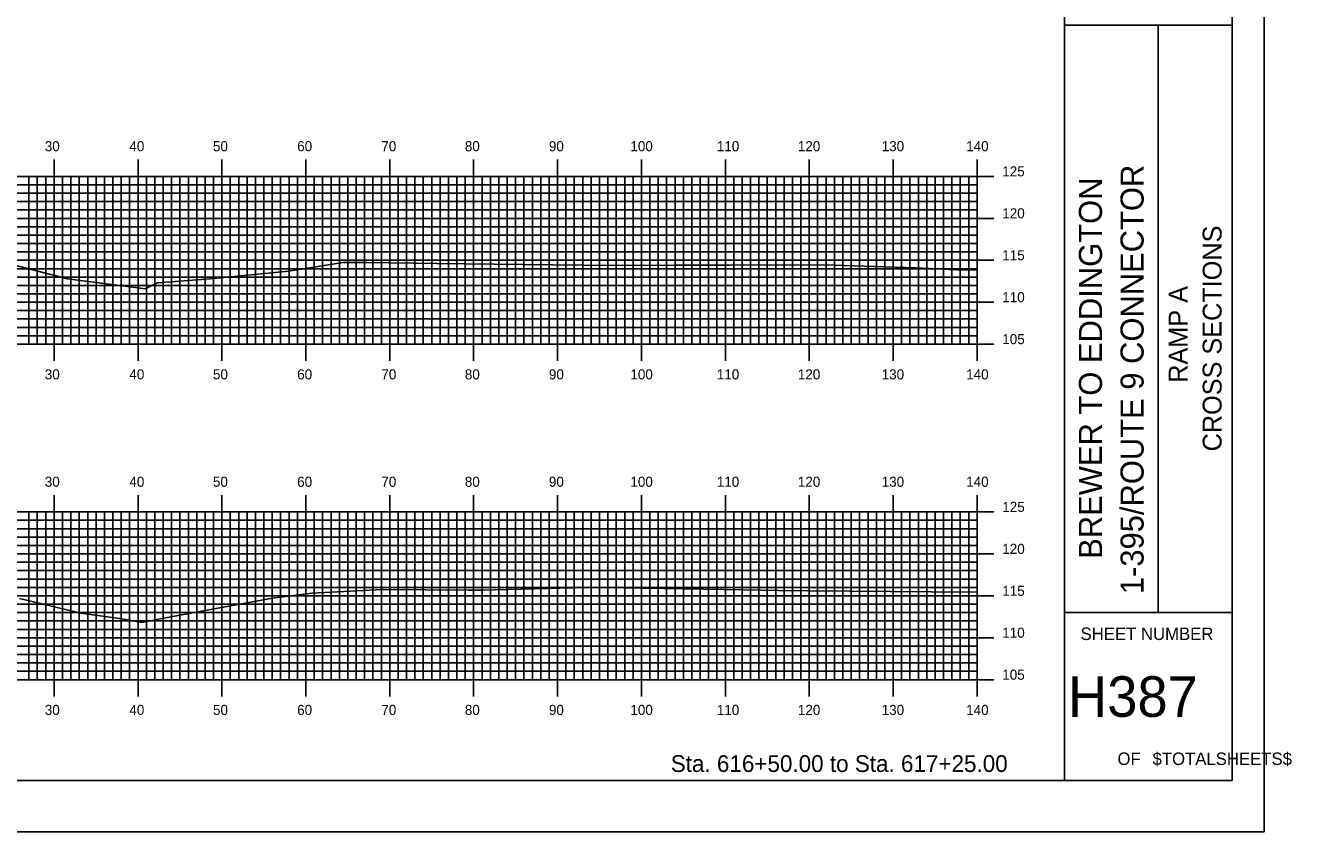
# Model space of a CAD drawing. Extents: x 844930 to 845273, y 363538 to 363758.
# Drawn here: x 845122 to 845273, y 363537.6 to 363633.7 of the extents above; entities that cross this region are included whole.
import ezdxf

# ---------------------------------------------------------------- set-up
doc = ezdxf.new("R2010")
doc.units = 0
for name, color, linetype in [('BORDER', 7, 'Continuous'), ('H_V ANNOTATION', 7, 'Continuous'), ('MAJOR', 7, 'Continuous'), ('MINOR', 7, 'Continuous'), ('PLOT BOUNDARY', 7, 'Continuous'), ('S_Roadway_Centerline', 7, 'Continuous')]:
    doc.layers.add(name, color=color, linetype=linetype)

msp = doc.modelspace()

# ---------------------------------------------------------------- linework, layer by layer
at = {"layer": 'BORDER'}
for p, q in [((845245.88, 363543.72), (845245.88, 363753.72)), ((845245.88, 363633.73), (845265.88, 363633.73)), ((845257.06, 363563.73), (845257.06, 363633.73)), ((845245.88, 363563.73), (845265.88, 363563.73))]:
    msp.add_line(p, q, dxfattribs=at)
msp.add_lwpolyline([(844945.88, 363543.72), (845265.88, 363543.72), (845265.88, 363753.72), (844945.88, 363753.72)], close=True, dxfattribs=at)
at = {"layer": 'MAJOR'}
for p, q in [((845125.48, 363617.73), (845125.48, 363615.72)), ((845135.48, 363617.73), (845135.48, 363615.72)), ((845145.48, 363617.73), (845145.48, 363615.72)), ((845155.48, 363617.73), (845155.48, 363615.72)), ((845165.48, 363617.73), (845165.48, 363615.72)), ((845175.48, 363617.73), (845175.48, 363615.72)), ((845185.48, 363617.73), (845185.48, 363615.72)), ((845195.48, 363617.73), (845195.48, 363615.72)), ((845205.48, 363617.73), (845205.48, 363615.72)), ((845215.48, 363617.73), (845215.48, 363615.72)), ((845225.48, 363617.73), (845225.48, 363615.72)), ((845235.48, 363617.73), (845235.48, 363615.72)), ((844955.48, 363615.72), (845235.48, 363615.72)), ((844955.48, 363615.72), (845235.48, 363615.72)), ((845125.48, 363595.72), (845125.48, 363615.72)), ((845135.48, 363595.72), (845135.48, 363615.72)), ((845145.48, 363595.72), (845145.48, 363615.72)), ((845155.48, 363595.72), (845155.48, 363615.72)), ((845165.48, 363595.72), (845165.48, 363615.72)), ((845175.48, 363595.72), (845175.48, 363615.72)), ((845185.48, 363595.72), (845185.48, 363615.72)), ((845195.48, 363595.72), (845195.48, 363615.72)), ((845205.48, 363595.72), (845205.48, 363615.72)), ((845215.48, 363595.72), (845215.48, 363615.72)), ((845225.48, 363595.72), (845225.48, 363615.72)), ((845237.48, 363615.72), (845233.47, 363615.72)), ((845235.48, 363595.72), (845235.48, 363615.72)), ((845235.48, 363595.72), (845235.48, 363615.72)), ((844955.48, 363610.72), (845235.48, 363610.72)), ((845237.48, 363610.72), (845233.47, 363610.72)), ((844955.48, 363605.72), (845235.48, 363605.72)), ((845237.48, 363605.72), (845233.47, 363605.72)), ((844955.48, 363600.72), (845235.48, 363600.72)), ((845237.48, 363600.72), (845233.47, 363600.72)), ((844955.48, 363595.72), (845235.48, 363595.72)), ((844955.48, 363595.72), (845235.48, 363595.72)), ((845125.48, 363593.72), (845125.48, 363595.72)), ((845135.48, 363593.72), (845135.48, 363595.72)), ((845145.48, 363593.72), (845145.48, 363595.72)), ((845155.48, 363593.72), (845155.48, 363595.72)), ((845165.48, 363593.72), (845165.48, 363595.72)), ((845175.48, 363593.72), (845175.48, 363595.72)), ((845185.48, 363593.72), (845185.48, 363595.72)), ((845195.48, 363593.72), (845195.48, 363595.72)), ((845205.48, 363593.72), (845205.48, 363595.72)), ((845215.48, 363593.72), (845215.48, 363595.72)), ((845225.48, 363593.72), (845225.48, 363595.72)), ((845237.48, 363595.72), (845233.47, 363595.72)), ((845235.48, 363593.72), (845235.48, 363595.72)), ((845125.48, 363577.73), (845125.48, 363575.72)), ((845135.48, 363577.73), (845135.48, 363575.72)), ((845145.48, 363577.73), (845145.48, 363575.72)), ((845155.48, 363577.73), (845155.48, 363575.72)), ((845165.48, 363577.73), (845165.48, 363575.72)), ((845175.48, 363577.73), (845175.48, 363575.72)), ((845185.48, 363577.73), (845185.48, 363575.72)), ((845195.48, 363577.73), (845195.48, 363575.72)), ((845205.48, 363577.73), (845205.48, 363575.72)), ((845215.48, 363577.73), (845215.48, 363575.72)), ((845225.48, 363577.73), (845225.48, 363575.72)), ((845235.48, 363577.73), (845235.48, 363575.72)), ((844955.48, 363575.72), (845235.48, 363575.72)), ((844955.48, 363575.72), (845235.48, 363575.72)), ((845125.48, 363555.72), (845125.48, 363575.72)), ((845135.48, 363555.72), (845135.48, 363575.72)), ((845145.48, 363555.72), (845145.48, 363575.72)), ((845155.48, 363555.72), (845155.48, 363575.72)), ((845165.48, 363555.72), (845165.48, 363575.72)), ((845175.48, 363555.72), (845175.48, 363575.72)), ((845185.48, 363555.72), (845185.48, 363575.72)), ((845195.48, 363555.72), (845195.48, 363575.72)), ((845205.48, 363555.72), (845205.48, 363575.72)), ((845215.48, 363555.72), (845215.48, 363575.72)), ((845225.48, 363555.72), (845225.48, 363575.72)), ((845237.48, 363575.72), (845233.47, 363575.72)), ((845235.48, 363555.72), (845235.48, 363575.72)), ((845235.48, 363555.72), (845235.48, 363575.72)), ((844955.48, 363570.72), (845235.48, 363570.72)), ((845237.48, 363570.72), (845233.47, 363570.72)), ((844955.48, 363565.72), (845235.48, 363565.72)), ((845237.48, 363565.72), (845233.47, 363565.72)), ((844955.48, 363560.72), (845235.48, 363560.72)), ((845237.48, 363560.72), (845233.47, 363560.72)), ((844955.48, 363555.72), (845235.48, 363555.72)), ((844955.48, 363555.72), (845235.48, 363555.72)), ((845125.48, 363553.72), (845125.48, 363555.72)), ((845135.48, 363553.72), (845135.48, 363555.72)), ((845145.48, 363553.72), (845145.48, 363555.72)), ((845155.48, 363553.72), (845155.48, 363555.72)), ((845165.48, 363553.72), (845165.48, 363555.72)), ((845175.48, 363553.72), (845175.48, 363555.72)), ((845185.48, 363553.72), (845185.48, 363555.72)), ((845195.48, 363553.72), (845195.48, 363555.72)), ((845205.48, 363553.72), (845205.48, 363555.72)), ((845215.48, 363553.72), (845215.48, 363555.72)), ((845225.48, 363553.72), (845225.48, 363555.72)), ((845237.48, 363555.72), (845233.47, 363555.72)), ((845235.48, 363553.72), (845235.48, 363555.72))]:
    msp.add_line(p, q, dxfattribs=at)
at = {"layer": 'MINOR'}
for p, q in [((845122.48, 363595.72), (845122.48, 363615.72)), ((845123.48, 363595.72), (845123.48, 363615.72)), ((845124.48, 363595.72), (845124.48, 363615.72)), ((845126.48, 363595.72), (845126.48, 363615.72)), ((845127.48, 363595.72), (845127.48, 363615.72)), ((845128.48, 363595.72), (845128.48, 363615.72)), ((845129.48, 363595.72), (845129.48, 363615.72)), ((845130.48, 363595.72), (845130.48, 363615.72)), ((845131.48, 363595.72), (845131.48, 363615.72)), ((845132.48, 363595.72), (845132.48, 363615.72)), ((845133.48, 363595.72), (845133.48, 363615.72)), ((845134.48, 363595.72), (845134.48, 363615.72)), ((845136.48, 363595.72), (845136.48, 363615.72)), ((845137.48, 363595.72), (845137.48, 363615.72)), ((845138.48, 363595.72), (845138.48, 363615.72)), ((845139.48, 363595.72), (845139.48, 363615.72)), ((845140.48, 363595.72), (845140.48, 363615.72)), ((845141.48, 363595.72), (845141.48, 363615.72)), ((845142.48, 363595.72), (845142.48, 363615.72)), ((845143.48, 363595.72), (845143.48, 363615.72)), ((845144.48, 363595.72), (845144.48, 363615.72)), ((845146.48, 363595.72), (845146.48, 363615.72)), ((845147.48, 363595.72), (845147.48, 363615.72)), ((845148.48, 363595.72), (845148.48, 363615.72)), ((845149.48, 363595.72), (845149.48, 363615.72)), ((845150.48, 363595.72), (845150.48, 363615.72)), ((845151.48, 363595.72), (845151.48, 363615.72)), ((845152.48, 363595.72), (845152.48, 363615.72)), ((845153.48, 363595.72), (845153.48, 363615.72)), ((845154.48, 363595.72), (845154.48, 363615.72)), ((845156.48, 363595.72), (845156.48, 363615.72)), ((845157.48, 363595.72), (845157.48, 363615.72)), ((845158.48, 363595.72), (845158.48, 363615.72)), ((845159.48, 363595.72), (845159.48, 363615.72)), ((845160.48, 363595.72), (845160.48, 363615.72)), ((845161.48, 363595.72), (845161.48, 363615.72)), ((845162.48, 363595.72), (845162.48, 363615.72)), ((845163.48, 363595.72), (845163.48, 363615.72)), ((845164.48, 363595.72), (845164.48, 363615.72)), ((845166.48, 363595.72), (845166.48, 363615.72)), ((845167.48, 363595.72), (845167.48, 363615.72)), ((845168.48, 363595.72), (845168.48, 363615.72)), ((845169.48, 363595.72), (845169.48, 363615.72)), ((845170.48, 363595.72), (845170.48, 363615.72)), ((845171.48, 363595.72), (845171.48, 363615.72)), ((845172.48, 363595.72), (845172.48, 363615.72)), ((845173.48, 363595.72), (845173.48, 363615.72)), ((845174.48, 363595.72), (845174.48, 363615.72)), ((845176.48, 363595.72), (845176.48, 363615.72)), ((845177.48, 363595.72), (845177.48, 363615.72)), ((845178.48, 363595.72), (845178.48, 363615.72)), ((845179.48, 363595.72), (845179.48, 363615.72)), ((845180.48, 363595.72), (845180.48, 363615.72)), ((845181.48, 363595.72), (845181.48, 363615.72)), ((845182.48, 363595.72), (845182.48, 363615.72)), ((845183.48, 363595.72), (845183.48, 363615.72)), ((845184.48, 363595.72), (845184.48, 363615.72)), ((845186.48, 363595.72), (845186.48, 363615.72)), ((845187.48, 363595.72), (845187.48, 363615.72)), ((845188.48, 363595.72), (845188.48, 363615.72)), ((845189.48, 363595.72), (845189.48, 363615.72)), ((845190.48, 363595.72), (845190.48, 363615.72)), ((845191.48, 363595.72), (845191.48, 363615.72)), ((845192.48, 363595.72), (845192.48, 363615.72)), ((845193.48, 363595.72), (845193.48, 363615.72)), ((845194.48, 363595.72), (845194.48, 363615.72)), ((845196.48, 363595.72), (845196.48, 363615.72)), ((845197.48, 363595.72), (845197.48, 363615.72)), ((845198.48, 363595.72), (845198.48, 363615.72)), ((845199.48, 363595.72), (845199.48, 363615.72)), ((845200.48, 363595.72), (845200.48, 363615.72)), ((845201.48, 363595.72), (845201.48, 363615.72)), ((845202.48, 363595.72), (845202.48, 363615.72)), ((845203.48, 363595.72), (845203.48, 363615.72)), ((845204.48, 363595.72), (845204.48, 363615.72)), ((845206.48, 363595.72), (845206.48, 363615.72)), ((845207.48, 363595.72), (845207.48, 363615.72)), ((845208.48, 363595.72), (845208.48, 363615.72)), ((845209.48, 363595.72), (845209.48, 363615.72)), ((845210.48, 363595.72), (845210.48, 363615.72)), ((845211.48, 363595.72), (845211.48, 363615.72)), ((845212.48, 363595.72), (845212.48, 363615.72)), ((845213.48, 363595.72), (845213.48, 363615.72)), ((845214.48, 363595.72), (845214.48, 363615.72)), ((845216.48, 363595.72), (845216.48, 363615.72)), ((845217.48, 363595.72), (845217.48, 363615.72)), ((845218.48, 363595.72), (845218.48, 363615.72)), ((845219.48, 363595.72), (845219.48, 363615.72)), ((845220.48, 363595.72), (845220.48, 363615.72)), ((845221.48, 363595.72), (845221.48, 363615.72)), ((845222.48, 363595.72), (845222.48, 363615.72)), ((845223.48, 363595.72), (845223.48, 363615.72)), ((845224.48, 363595.72), (845224.48, 363615.72)), ((845226.48, 363595.72), (845226.48, 363615.72)), ((845227.48, 363595.72), (845227.48, 363615.72)), ((845228.48, 363595.72), (845228.48, 363615.72)), ((845229.48, 363595.72), (845229.48, 363615.72)), ((845230.48, 363595.72), (845230.48, 363615.72)), ((845231.48, 363595.72), (845231.48, 363615.72)), ((845232.48, 363595.72), (845232.48, 363615.72)), ((845233.48, 363595.72), (845233.48, 363615.72)), ((845234.48, 363595.72), (845234.48, 363615.72)), ((844955.48, 363614.72), (845235.48, 363614.72)), ((845235.48, 363614.72), (845233.47, 363614.72)), ((844955.48, 363613.72), (845235.48, 363613.72)), ((844955.48, 363612.72), (845235.48, 363612.72)), ((845235.48, 363613.72), (845233.47, 363613.72)), ((845235.48, 363612.72), (845233.47, 363612.72)), ((844955.48, 363611.72), (845235.48, 363611.72)), ((845235.48, 363611.72), (845233.47, 363611.72)), ((844955.48, 363609.72), (845235.48, 363609.72)), ((845235.48, 363609.72), (845233.47, 363609.72)), ((844955.48, 363608.72), (845235.48, 363608.72)), ((845235.48, 363608.72), (845233.47, 363608.72)), ((844955.48, 363607.72), (845235.48, 363607.72)), ((844955.48, 363606.72), (845235.48, 363606.72)), ((845235.48, 363607.72), (845233.47, 363607.72)), ((845235.48, 363606.72), (845233.47, 363606.72)), ((844955.48, 363604.72), (845235.48, 363604.72)), ((844955.48, 363603.72), (845235.48, 363603.72)), ((845235.48, 363604.72), (845233.47, 363604.72)), ((845235.48, 363603.72), (845233.47, 363603.72)), ((844955.48, 363602.72), (845235.48, 363602.72)), ((845235.48, 363602.72), (845233.47, 363602.72)), ((844955.48, 363601.72), (845235.48, 363601.72)), ((845235.48, 363601.72), (845233.47, 363601.72)), ((844955.48, 363599.72), (845235.48, 363599.72)), ((845235.48, 363599.72), (845233.47, 363599.72)), ((844955.48, 363598.72), (845235.48, 363598.72)), ((844955.48, 363597.72), (845235.48, 363597.72)), ((845235.48, 363598.72), (845233.47, 363598.72)), ((845235.48, 363597.72), (845233.47, 363597.72)), ((844955.48, 363596.72), (845235.48, 363596.72)), ((845235.48, 363596.72), (845233.47, 363596.72)), ((845122.48, 363555.72), (845122.48, 363575.72)), ((845123.48, 363555.72), (845123.48, 363575.72)), ((845124.48, 363555.72), (845124.48, 363575.72)), ((845126.48, 363555.72), (845126.48, 363575.72)), ((845127.48, 363555.72), (845127.48, 363575.72)), ((845128.48, 363555.72), (845128.48, 363575.72)), ((845129.48, 363555.72), (845129.48, 363575.72)), ((845130.48, 363555.72), (845130.48, 363575.72)), ((845131.48, 363555.72), (845131.48, 363575.72)), ((845132.48, 363555.72), (845132.48, 363575.72)), ((845133.48, 363555.72), (845133.48, 363575.72)), ((845134.48, 363555.72), (845134.48, 363575.72)), ((845136.48, 363555.72), (845136.48, 363575.72)), ((845137.48, 363555.72), (845137.48, 363575.72)), ((845138.48, 363555.72), (845138.48, 363575.72)), ((845139.48, 363555.72), (845139.48, 363575.72)), ((845140.48, 363555.72), (845140.48, 363575.72)), ((845141.48, 363555.72), (845141.48, 363575.72)), ((845142.48, 363555.72), (845142.48, 363575.72)), ((845143.48, 363555.72), (845143.48, 363575.72)), ((845144.48, 363555.72), (845144.48, 363575.72)), ((845146.48, 363555.72), (845146.48, 363575.72)), ((845147.48, 363555.72), (845147.48, 363575.72)), ((845148.48, 363555.72), (845148.48, 363575.72)), ((845149.48, 363555.72), (845149.48, 363575.72)), ((845150.48, 363555.72), (845150.48, 363575.72)), ((845151.48, 363555.72), (845151.48, 363575.72)), ((845152.48, 363555.72), (845152.48, 363575.72)), ((845153.48, 363555.72), (845153.48, 363575.72)), ((845154.48, 363555.72), (845154.48, 363575.72)), ((845156.48, 363555.72), (845156.48, 363575.72)), ((845157.48, 363555.72), (845157.48, 363575.72)), ((845158.48, 363555.72), (845158.48, 363575.72)), ((845159.48, 363555.72), (845159.48, 363575.72)), ((845160.48, 363555.72), (845160.48, 363575.72)), ((845161.48, 363555.72), (845161.48, 363575.72)), ((845162.48, 363555.72), (845162.48, 363575.72)), ((845163.48, 363555.72), (845163.48, 363575.72)), ((845164.48, 363555.72), (845164.48, 363575.72)), ((845166.48, 363555.72), (845166.48, 363575.72)), ((845167.48, 363555.72), (845167.48, 363575.72)), ((845168.48, 363555.72), (845168.48, 363575.72)), ((845169.48, 363555.72), (845169.48, 363575.72)), ((845170.48, 363555.72), (845170.48, 363575.72)), ((845171.48, 363555.72), (845171.48, 363575.72)), ((845172.48, 363555.72), (845172.48, 363575.72)), ((845173.48, 363555.72), (845173.48, 363575.72)), ((845174.48, 363555.72), (845174.48, 363575.72)), ((845176.48, 363555.72), (845176.48, 363575.72)), ((845177.48, 363555.72), (845177.48, 363575.72)), ((845178.48, 363555.72), (845178.48, 363575.72)), ((845179.48, 363555.72), (845179.48, 363575.72)), ((845180.48, 363555.72), (845180.48, 363575.72)), ((845181.48, 363555.72), (845181.48, 363575.72)), ((845182.48, 363555.72), (845182.48, 363575.72)), ((845183.48, 363555.72), (845183.48, 363575.72)), ((845184.48, 363555.72), (845184.48, 363575.72)), ((845186.48, 363555.72), (845186.48, 363575.72)), ((845187.48, 363555.72), (845187.48, 363575.72)), ((845188.48, 363555.72), (845188.48, 363575.72)), ((845189.48, 363555.72), (845189.48, 363575.72)), ((845190.48, 363555.72), (845190.48, 363575.72)), ((845191.48, 363555.72), (845191.48, 363575.72)), ((845192.48, 363555.72), (845192.48, 363575.72)), ((845193.48, 363555.72), (845193.48, 363575.72)), ((845194.48, 363555.72), (845194.48, 363575.72)), ((845196.48, 363555.72), (845196.48, 363575.72)), ((845197.48, 363555.72), (845197.48, 363575.72)), ((845198.48, 363555.72), (845198.48, 363575.72)), ((845199.48, 363555.72), (845199.48, 363575.72)), ((845200.48, 363555.72), (845200.48, 363575.72)), ((845201.48, 363555.72), (845201.48, 363575.72)), ((845202.48, 363555.72), (845202.48, 363575.72)), ((845203.48, 363555.72), (845203.48, 363575.72)), ((845204.48, 363555.72), (845204.48, 363575.72)), ((845206.48, 363555.72), (845206.48, 363575.72)), ((845207.48, 363555.72), (845207.48, 363575.72)), ((845208.48, 363555.72), (845208.48, 363575.72)), ((845209.48, 363555.72), (845209.48, 363575.72)), ((845210.48, 363555.72), (845210.48, 363575.72)), ((845211.48, 363555.72), (845211.48, 363575.72)), ((845212.48, 363555.72), (845212.48, 363575.72)), ((845213.48, 363555.72), (845213.48, 363575.72)), ((845214.48, 363555.72), (845214.48, 363575.72)), ((845216.48, 363555.72), (845216.48, 363575.72)), ((845217.48, 363555.72), (845217.48, 363575.72)), ((845218.48, 363555.72), (845218.48, 363575.72)), ((845219.48, 363555.72), (845219.48, 363575.72)), ((845220.48, 363555.72), (845220.48, 363575.72)), ((845221.48, 363555.72), (845221.48, 363575.72)), ((845222.48, 363555.72), (845222.48, 363575.72)), ((845223.48, 363555.72), (845223.48, 363575.72)), ((845224.48, 363555.72), (845224.48, 363575.72)), ((845226.48, 363555.72), (845226.48, 363575.72)), ((845227.48, 363555.72), (845227.48, 363575.72)), ((845228.48, 363555.72), (845228.48, 363575.72)), ((845229.48, 363555.72), (845229.48, 363575.72)), ((845230.48, 363555.72), (845230.48, 363575.72)), ((845231.48, 363555.72), (845231.48, 363575.72)), ((845232.48, 363555.72), (845232.48, 363575.72)), ((845233.48, 363555.72), (845233.48, 363575.72)), ((845234.48, 363555.72), (845234.48, 363575.72)), ((844955.48, 363574.72), (845235.48, 363574.72)), ((844955.48, 363573.72), (845235.48, 363573.72)), ((845235.48, 363574.72), (845233.47, 363574.72)), ((845235.48, 363573.72), (845233.47, 363573.72)), ((844955.48, 363572.72), (845235.48, 363572.72)), ((845235.48, 363572.72), (845233.47, 363572.72)), ((844955.48, 363571.72), (845235.48, 363571.72)), ((845235.48, 363571.72), (845233.47, 363571.72)), ((844955.48, 363569.72), (845235.48, 363569.72)), ((845235.48, 363569.72), (845233.47, 363569.72)), ((844955.48, 363568.72), (845235.48, 363568.72)), ((844955.48, 363567.72), (845235.48, 363567.72)), ((845235.48, 363568.72), (845233.47, 363568.72)), ((845235.48, 363567.72), (845233.47, 363567.72)), ((844955.48, 363566.72), (845235.48, 363566.72)), ((845235.48, 363566.72), (845233.47, 363566.72)), ((844955.48, 363564.72), (845235.48, 363564.72)), ((845235.48, 363564.72), (845233.47, 363564.72)), ((844955.48, 363563.72), (845235.48, 363563.72)), ((844955.48, 363562.72), (845235.48, 363562.72)), ((845235.48, 363563.72), (845233.47, 363563.72)), ((845235.48, 363562.72), (845233.47, 363562.72)), ((844955.48, 363561.72), (845235.48, 363561.72)), ((845235.48, 363561.72), (845233.47, 363561.72)), ((844955.48, 363559.72), (845235.48, 363559.72)), ((845235.48, 363559.72), (845233.47, 363559.72)), ((844955.48, 363558.72), (845235.48, 363558.72)), ((845235.48, 363558.72), (845233.47, 363558.72)), ((844955.48, 363557.72), (845235.48, 363557.72)), ((844955.48, 363556.72), (845235.48, 363556.72)), ((845235.48, 363557.72), (845233.47, 363557.72)), ((845235.48, 363556.72), (845233.47, 363556.72))]:
    msp.add_line(p, q, dxfattribs=at)
at = {"layer": 'PLOT BOUNDARY'}
msp.add_lwpolyline([(844929.69, 363537.6), (845269.69, 363537.6), (845269.69, 363757.6), (844929.69, 363757.6)], close=True, dxfattribs=at)
at = {"layer": 'S_Roadway_Centerline'}
for points in [[(845118.72, 363605.64), (845127.06, 363603.52), (845129.54, 363603.19), (845135.48, 363602.43), (845136.34, 363602.32), (845137.82, 363603.05), (845144.09, 363603.5), (845153.41, 363604.42), (845159.88, 363605.46), (845162.78, 363605.44), (845171.09, 363605.35), (845181.39, 363605.22), (845191.89, 363605.1), (845199.38, 363605.12), (845206, 363605.13), (845217.18, 363605.18), (845228.2, 363604.82), (845233, 363604.59), (845235.48, 363604.54)], [(845121.35, 363565.42), (845128.67, 363563.67), (845133.56, 363562.96), (845135.93, 363562.55), (845139.6, 363563.25), (845140.05, 363563.32), (845141.97, 363563.7), (845151.5, 363565.46), (845156.19, 363566.02), (845164.62, 363566.48), (845174.89, 363566.39), (845176.41, 363566.4), (845179.6, 363566.48), (845188.86, 363566.7), (845193.34, 363566.68), (845207.64, 363566.42), (845211.81, 363566.36), (845215.46, 363566.33), (845230.02, 363566.2), (845235.48, 363566.17)]]:
    msp.add_lwpolyline(points, dxfattribs=at)

# ---------------------------------------------------------------- texts
at = {"layer": 'BORDER'}
for s, height, p in [('1-395/ROUTE 9 CONNECTOR', 2.7557, (845255.33, 363565.92)), ('BREWER TO EDDINGTON', 2.7557, (845250.37, 363570.13)), ('CROSS SECTIONS', 2.25, (845264.62, 363582.94)), ('RAMP A', 2.25, (845260.57, 363591.12))]:
    msp.add_text(s, height=height, rotation=90, dxfattribs=at).set_placement(p)
for s, height, p in [('SHEET NUMBER', 1.4905, (845247.81, 363560.45)), ('H387', 4.839, (845246.32, 363551.29)), ('OF', 1.491, (845252.21, 363545.55)), ('$TOTALSHEETS$', 1.4905, (845256.39, 363545.55))]:
    msp.add_text(s, height=height, dxfattribs=at).set_placement(p)
at = {"layer": 'H_V ANNOTATION'}
for s, height, p in [('30', 1.2, (845124.37, 363618.72)), ('40', 1.2, (845134.45, 363618.72)), ('50', 1.2, (845144.41, 363618.72)), ('60', 1.2, (845154.45, 363618.72)), ('70', 1.2, (845164.48, 363618.72)), ('80', 1.2, (845174.43, 363618.72)), ('90', 1.2, (845184.45, 363618.72)), ('100', 1.2, (845194.16, 363618.72)), ('110', 1.2, (845204.46, 363618.72)), ('120', 1.2, (845214.12, 363618.72)), ('130', 1.2, (845224.11, 363618.72)), ('140', 1.2, (845234.18, 363618.72)), ('125', 1.2, (845238.48, 363615.72)), ('120', 1.2, (845238.48, 363610.72)), ('115', 1.2, (845238.48, 363605.72)), ('110', 1.2, (845238.48, 363600.72)), ('105', 1.2, (845238.48, 363595.72)), ('30', 1.2, (845124.37, 363591.52)), ('40', 1.2, (845134.45, 363591.52)), ('50', 1.2, (845144.41, 363591.52)), ('60', 1.2, (845154.45, 363591.52)), ('70', 1.2, (845164.48, 363591.52)), ('80', 1.2, (845174.43, 363591.52)), ('90', 1.2, (845184.45, 363591.52)), ('100', 1.2, (845194.16, 363591.52)), ('110', 1.2, (845204.46, 363591.52)), ('120', 1.2, (845214.12, 363591.52)), ('130', 1.2, (845224.11, 363591.52)), ('140', 1.2, (845234.18, 363591.52)), ('30', 1.2, (845124.37, 363578.72)), ('40', 1.2, (845134.45, 363578.72)), ('50', 1.2, (845144.41, 363578.72)), ('60', 1.2, (845154.45, 363578.72)), ('70', 1.2, (845164.48, 363578.72)), ('80', 1.2, (845174.43, 363578.72)), ('90', 1.2, (845184.45, 363578.72)), ('100', 1.2, (845194.16, 363578.72)), ('110', 1.2, (845204.46, 363578.72)), ('120', 1.2, (845214.12, 363578.72)), ('130', 1.2, (845224.11, 363578.72)), ('140', 1.2, (845234.18, 363578.72)), ('125', 1.2, (845238.48, 363575.72)), ('120', 1.2, (845238.48, 363570.72)), ('115', 1.2, (845238.48, 363565.72)), ('110', 1.2, (845238.48, 363560.72)), ('105', 1.2, (845238.48, 363555.72)), ('30', 1.2, (845124.37, 363551.52)), ('40', 1.2, (845134.45, 363551.52)), ('50', 1.2, (845144.41, 363551.52)), ('60', 1.2, (845154.45, 363551.52)), ('70', 1.2, (845164.48, 363551.52)), ('80', 1.2, (845174.43, 363551.52)), ('90', 1.2, (845184.45, 363551.52)), ('100', 1.2, (845194.16, 363551.52)), ('110', 1.2, (845204.46, 363551.52)), ('120', 1.2, (845214.12, 363551.52)), ('130', 1.2, (845224.11, 363551.52)), ('140', 1.2, (845234.18, 363551.52)), ('Sta. 616+50.00 to Sta. 617+25.00', 2.0004, (845198.97, 363544.72))]:
    msp.add_text(s, height=height, dxfattribs=at).set_placement(p)

doc.saveas('drawing.dxf')
